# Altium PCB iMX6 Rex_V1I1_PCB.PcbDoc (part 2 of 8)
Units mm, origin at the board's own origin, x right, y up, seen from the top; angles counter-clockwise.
Board outline 70 x 40 mm, 12 copper layers (L1, L2, L3, L4, L5 (PWR), L6 (PWR), L7 (PWR), L8 (PWR), L9, L10, L11, L12), stack 1.566 mm thick; 473 components, 409 nets, 2294 pads, 1880 vias.
Unrouted connection lines stored in the file: 7.
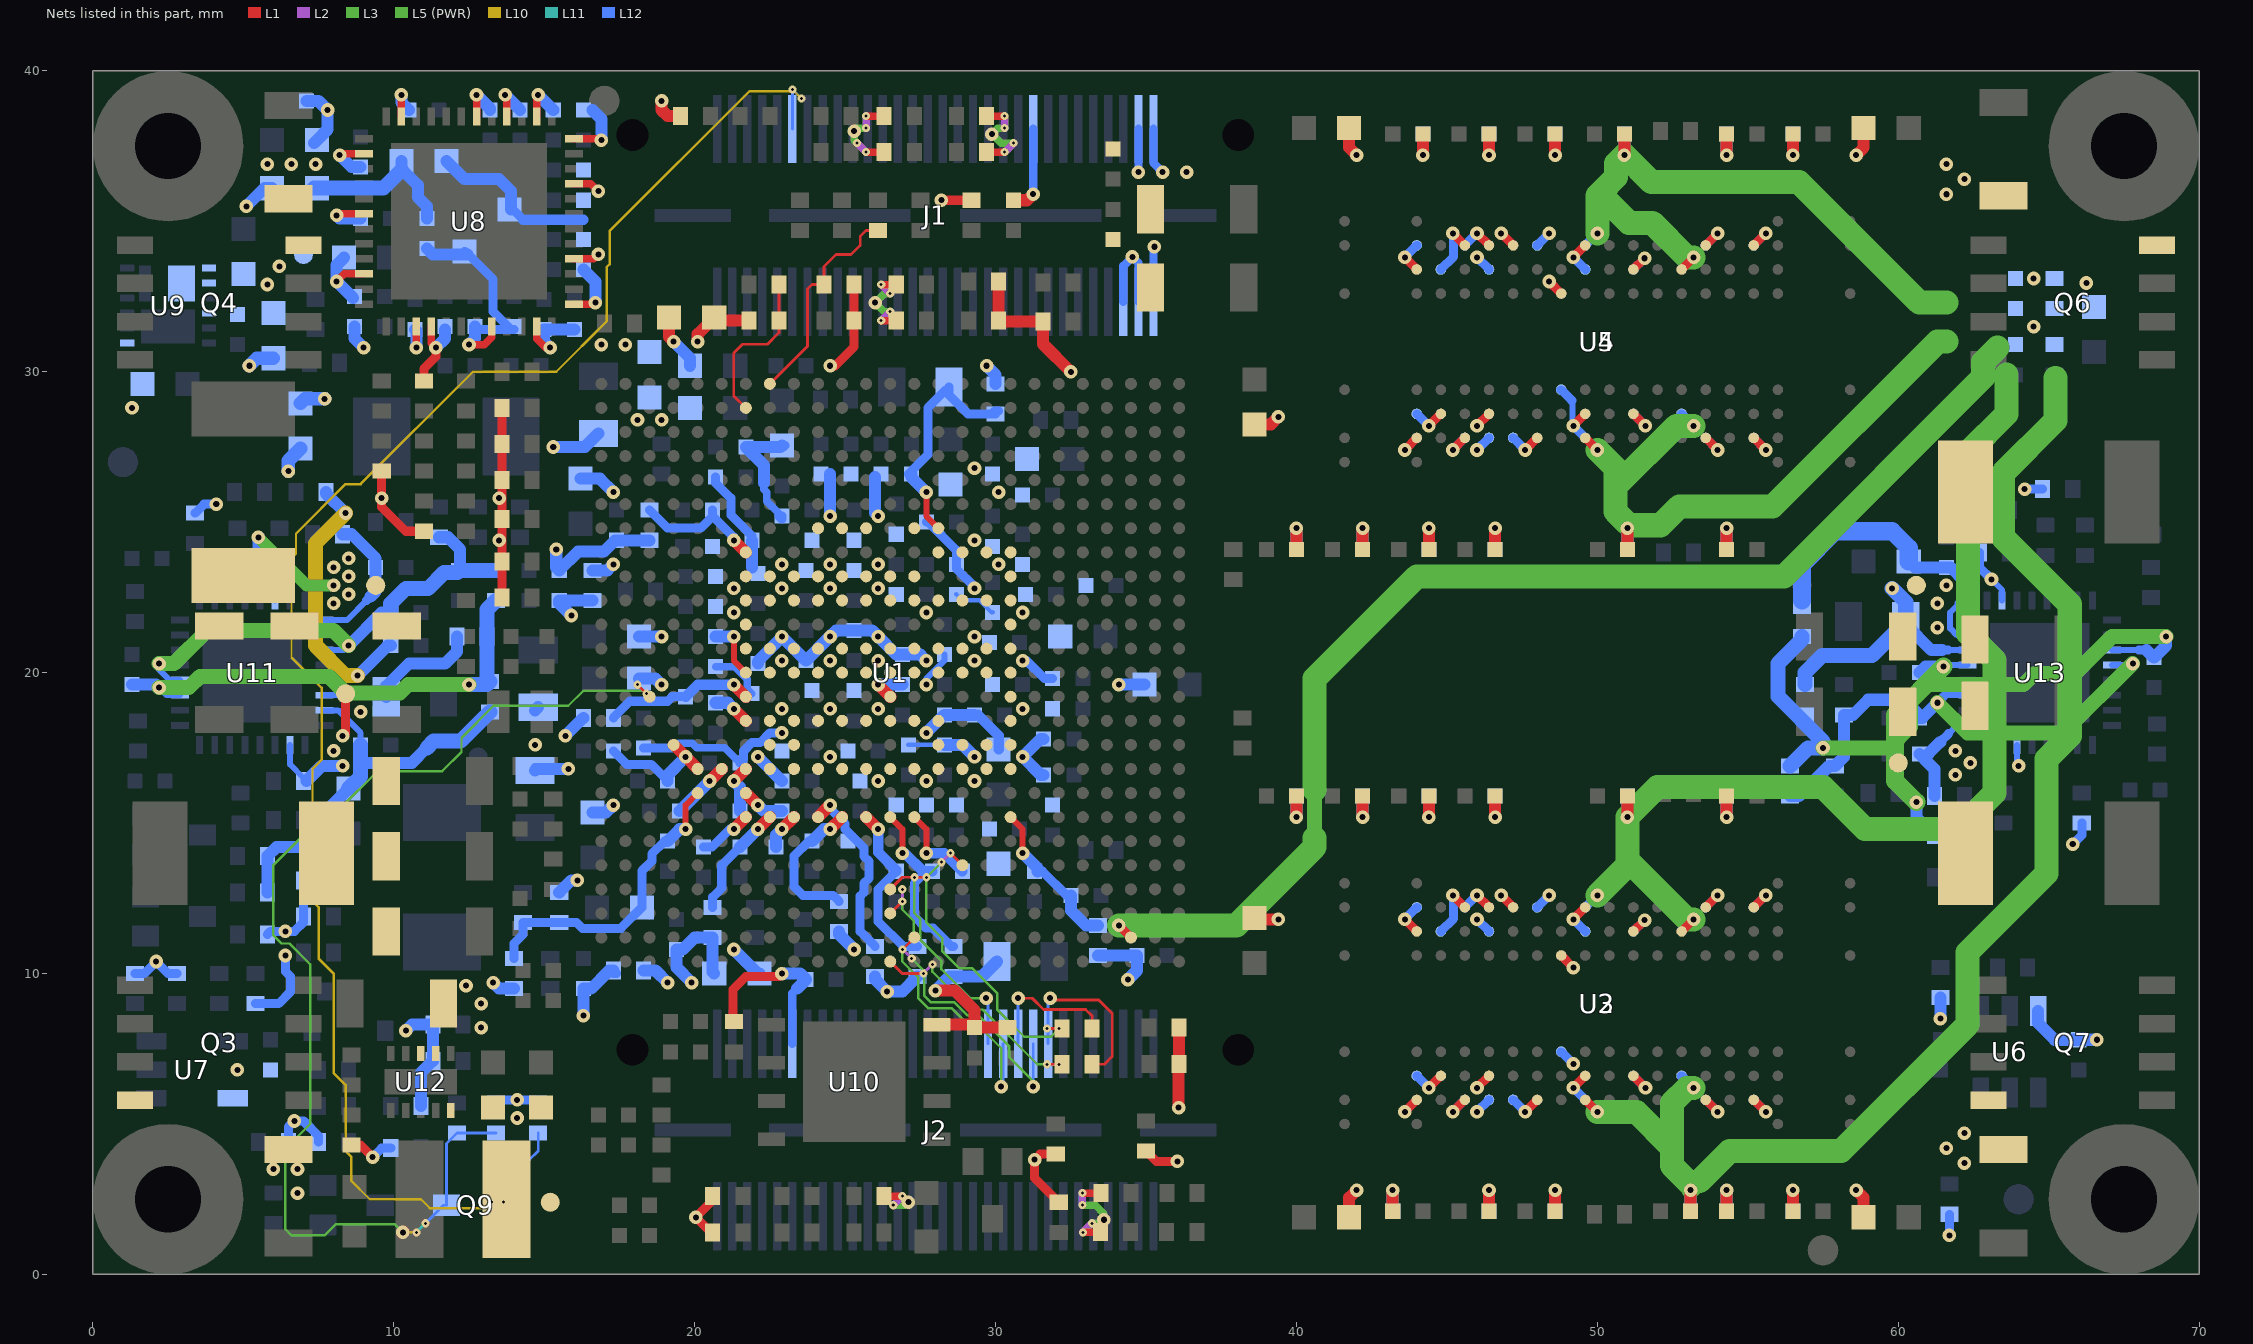
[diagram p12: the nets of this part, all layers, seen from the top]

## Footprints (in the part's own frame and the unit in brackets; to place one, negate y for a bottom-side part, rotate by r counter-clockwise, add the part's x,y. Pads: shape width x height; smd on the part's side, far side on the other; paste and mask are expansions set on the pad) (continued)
PBGA624 [mm] "Creator MM"
  round 0.4 smd mask+0.05: A2(-8.8,9.6) A3(-8,9.6) A4(-7.2,9.6) A5(-6.4,9.6) A6(-5.6,9.6) A7(-4.8,9.6) A8(-4,9.6) A9(-3.2,9.6) A10(-2.4,9.6) A11(-1.6,9.6) A12(-0.8,9.6) A13(0,9.6) A14(0.8,9.6) A15(1.6,9.6) A16(2.4,9.6) A17(3.2,9.6) A18(4,9.6) A19(4.8,9.6) A20(5.6,9.6) A21(6.4,9.6) A22(7.2,9.6) A23(8,9.6) A24(8.8,9.6) A25(9.6,9.6) AA1(-9.6,-6.4) AA2(-8.8,-6.4) AA3(-8,-6.4) AA4(-7.2,-6.4) AA5(-6.4,-6.4) AA6(-5.6,-6.4) AA7(-4.8,-6.4) AA8(-4,-6.4) AA9(-3.2,-6.4) AA10(-2.4,-6.4) AA11(-1.6,-6.4) AA12(-0.8,-6.4) AA13(0,-6.4) AA14(0.8,-6.4) AA15(1.6,-6.4) AA16(2.4,-6.4) AA17(3.2,-6.4) AA18(4,-6.4) AA19(4.8,-6.4) AA20(5.6,-6.4) AA21(6.4,-6.4) AA22(7.2,-6.4) AA23(8,-6.4) AA24(8.8,-6.4) AA25(9.6,-6.4) AB1(-9.6,-7.2) AB2(-8.8,-7.2) AB3(-8,-7.2) AB4(-7.2,-7.2) AB5(-6.4,-7.2) AB6(-5.6,-7.2) AB7(-4.8,-7.2) AB8(-4,-7.2) AB9(-3.2,-7.2) AB10(-2.4,-7.2) AB11(-1.6,-7.2) AB12(-0.8,-7.2) AB13(0,-7.2) AB14(0.8,-7.2) AB15(1.6,-7.2) AB16(2.4,-7.2) AB17(3.2,-7.2) AB18(4,-7.2) AB19(4.8,-7.2) AB20(5.6,-7.2) AB21(6.4,-7.2) AB22(7.2,-7.2) AB23(8,-7.2) AB24(8.8,-7.2) AB25(9.6,-7.2) AC1(-9.6,-8) AC2(-8.8,-8) AC3(-8,-8) AC4(-7.2,-8) AC5(-6.4,-8) AC6(-5.6,-8) AC7(-4.8,-8) AC8(-4,-8) AC9(-3.2,-8) AC10(-2.4,-8) AC11(-1.6,-8) AC12(-0.8,-8) AC13(0,-8) AC14(0.8,-8) AC15(1.6,-8) AC16(2.4,-8) AC17(3.2,-8) AC18(4,-8) AC19(4.8,-8) AC20(5.6,-8) AC21(6.4,-8) AC22(7.2,-8) AC23(8,-8) AC24(8.8,-8) AC25(9.6,-8) AD1(-9.6,-8.8) AD2(-8.8,-8.8) AD3(-8,-8.8) AD4(-7.2,-8.8) AD5(-6.4,-8.8) AD6(-5.6,-8.8) AD7(-4.8,-8.8) AD8(-4,-8.8) AD9(-3.2,-8.8) AD10(-2.4,-8.8) AD11(-1.6,-8.8) AD12(-0.8,-8.8) AD13(0,-8.8) AD14(0.8,-8.8) AD15(1.6,-8.8) AD16(2.4,-8.8) AD17(3.2,-8.8) AD18(4,-8.8) AD19(4.8,-8.8) AD20(5.6,-8.8) AD21(6.4,-8.8) AD22(7.2,-8.8) AD23(8,-8.8) AD24(8.8,-8.8) AD25(9.6,-8.8) AE1(-9.6,-9.6) AE2(-8.8,-9.6) AE3(-8,-9.6) AE4(-7.2,-9.6) AE5(-6.4,-9.6) AE6(-5.6,-9.6) AE7(-4.8,-9.6) AE8(-4,-9.6) AE9(-3.2,-9.6) AE10(-2.4,-9.6) AE11(-1.6,-9.6) AE12(-0.8,-9.6) AE13(0,-9.6) AE14(0.8,-9.6) AE15(1.6,-9.6) AE16(2.4,-9.6) AE17(3.2,-9.6) AE18(4,-9.6) AE19(4.8,-9.6) AE20(5.6,-9.6) AE21(6.4,-9.6) AE22(7.2,-9.6) AE23(8,-9.6) AE24(8.8,-9.6) AE25(9.6,-9.6) B1(-9.6,8.8) B2(-8.8,8.8) B3(-8,8.8) B4(-7.2,8.8) B5(-6.4,8.8) B6(-5.6,8.8) B7(-4.8,8.8) B8(-4,8.8) B9(-3.2,8.8) B10(-2.4,8.8) B11(-1.6,8.8) B12(-0.8,8.8) B13(0,8.8) B14(0.8,8.8) B15(1.6,8.8) B16(2.4,8.8) B17(3.2,8.8) B18(4,8.8) B19(4.8,8.8) B20(5.6,8.8) B21(6.4,8.8) B22(7.2,8.8) B23(8,8.8) B24(8.8,8.8) B25(9.6,8.8) C1(-9.6,8) C2(-8.8,8) C3(-8,8) C4(-7.2,8) C5(-6.4,8) C6(-5.6,8) C7(-4.8,8) C8(-4,8) C9(-3.2,8) C10(-2.4,8) C11(-1.6,8) C12(-0.8,8) C13(0,8) C14(0.8,8) C15(1.6,8) C16(2.4,8) C17(3.2,8) C18(4,8) C19(4.8,8) C20(5.6,8) C21(6.4,8) C22(7.2,8) C23(8,8) C24(8.8,8) C25(9.6,8) D1(-9.6,7.2) D2(-8.8,7.2) D3(-8,7.2) D4(-7.2,7.2) D5(-6.4,7.2) D6(-5.6,7.2) D7(-4.8,7.2) D8(-4,7.2) D9(-3.2,7.2) D10(-2.4,7.2) D11(-1.6,7.2) D12(-0.8,7.2) D13(0,7.2) D14(0.8,7.2) D15(1.6,7.2) D16(2.4,7.2) D17(3.2,7.2) D18(4,7.2) D19(4.8,7.2) D20(5.6,7.2) D21(6.4,7.2) D22(7.2,7.2) D23(8,7.2) D24(8.8,7.2) D25(9.6,7.2) E1(-9.6,6.4) E2(-8.8,6.4) E3(-8,6.4) E4(-7.2,6.4) E5(-6.4,6.4) E6(-5.6,6.4) E7(-4.8,6.4) E8(-4,6.4) E9(-3.2,6.4) E10(-2.4,6.4) E11(-1.6,6.4) E12(-0.8,6.4) E13(0,6.4) E14(0.8,6.4) E15(1.6,6.4) E16(2.4,6.4) E17(3.2,6.4) E18(4,6.4) E19(4.8,6.4) E20(5.6,6.4) E21(6.4,6.4) E22(7.2,6.4) E23(8,6.4) E24(8.8,6.4) E25(9.6,6.4) F1(-9.6,5.6) F2(-8.8,5.6) F3(-8,5.6) F4(-7.2,5.6) F5(-6.4,5.6) F6(-5.6,5.6) F7(-4.8,5.6) F8(-4,5.6) F9(-3.2,5.6) F10(-2.4,5.6) F11(-1.6,5.6) F12(-0.8,5.6) F13(0,5.6) F14(0.8,5.6) F15(1.6,5.6) F16(2.4,5.6) F17(3.2,5.6) F18(4,5.6) F19(4.8,5.6) F20(5.6,5.6) F21(6.4,5.6) F22(7.2,5.6) F23(8,5.6) F24(8.8,5.6) F25(9.6,5.6) G1(-9.6,4.8) G2(-8.8,4.8) G3(-8,4.8) G4(-7.2,4.8) G5(-6.4,4.8) G6(-5.6,4.8) G7(-4.8,4.8) G8(-4,4.8) G9(-3.2,4.8) G10(-2.4,4.8) G11(-1.6,4.8) G12(-0.8,4.8) G13(0,4.8) G14(0.8,4.8) G15(1.6,4.8) G16(2.4,4.8) G17(3.2,4.8) G18(4,4.8) G19(4.8,4.8) G20(5.6,4.8) G21(6.4,4.8) G22(7.2,4.8) G23(8,4.8) G24(8.8,4.8) G25(9.6,4.8) H1(-9.6,4) H2(-8.8,4) H3(-8,4) H4(-7.2,4) H5(-6.4,4) H6(-5.6,4) H7(-4.8,4) H8(-4,4) H9(-3.2,4) H10(-2.4,4) H11(-1.6,4) H12(-0.8,4) H13(0,4) H14(0.8,4) H15(1.6,4) H16(2.4,4) H17(3.2,4) H18(4,4) H19(4.8,4) H20(5.6,4) H21(6.4,4) H22(7.2,4) H23(8,4) H24(8.8,4) H25(9.6,4) J1(-9.6,3.2) J2(-8.8,3.2) J3(-8,3.2) J4(-7.2,3.2) J5(-6.4,3.2) J6(-5.6,3.2) J7(-4.8,3.2) J8(-4,3.2) J9(-3.2,3.2) J10(-2.4,3.2) J11(-1.6,3.2) J12(-0.8,3.2) J13(0,3.2) J14(0.8,3.2) J15(1.6,3.2) J16(2.4,3.2) J17(3.2,3.2) J18(4,3.2) J19(4.8,3.2) J20(5.6,3.2) J21(6.4,3.2) J22(7.2,3.2) J23(8,3.2) J24(8.8,3.2) J25(9.6,3.2) K1(-9.6,2.4) K2(-8.8,2.4) K3(-8,2.4) K4(-7.2,2.4) K5(-6.4,2.4) K6(-5.6,2.4) K7(-4.8,2.4) K8(-4,2.4) K9(-3.2,2.4) K10(-2.4,2.4) K11(-1.6,2.4) K12(-0.8,2.4) K13(0,2.4) K14(0.8,2.4) K15(1.6,2.4) K16(2.4,2.4) K17(3.2,2.4) K18(4,2.4) K19(4.8,2.4) K20(5.6,2.4) K21(6.4,2.4) K22(7.2,2.4) K23(8,2.4) K24(8.8,2.4) K25(9.6,2.4) L1(-9.6,1.6) L2(-8.8,1.6) L3(-8,1.6) L4(-7.2,1.6) L5(-6.4,1.6) L6(-5.6,1.6) L7(-4.8,1.6) L8(-4,1.6) L9(-3.2,1.6) L10(-2.4,1.6) L11(-1.6,1.6) L12(-0.8,1.6) L13(0,1.6) L14(0.8,1.6) L15(1.6,1.6) L16(2.4,1.6) L17(3.2,1.6) L18(4,1.6) L19(4.8,1.6) L20(5.6,1.6) L21(6.4,1.6) L22(7.2,1.6) L23(8,1.6) L24(8.8,1.6) L25(9.6,1.6) M1(-9.6,0.8) M2(-8.8,0.8) M3(-8,0.8) M4(-7.2,0.8) M5(-6.4,0.8) M6(-5.6,0.8) M7(-4.8,0.8) M8(-4,0.8) M9(-3.2,0.8) M10(-2.4,0.8) M11(-1.6,0.8) M12(-0.8,0.8) M13(0,0.8) M14(0.8,0.8) M15(1.6,0.8) M16(2.4,0.8) M17(3.2,0.8) M18(4,0.8) M19(4.8,0.8) M20(5.6,0.8) M21(6.4,0.8) M22(7.2,0.8) M23(8,0.8) M24(8.8,0.8) M25(9.6,0.8) N1(-9.6,0) N2(-8.8,0) N3(-8,0) N4(-7.2,0) N5(-6.4,0) N6(-5.6,0) N7(-4.8,0) N8(-4,0) N9(-3.2,0) N10(-2.4,0) N11(-1.6,0) N12(-0.8,0) N13(0,0) N14(0.8,0) N15(1.6,0) N16(2.4,0) N17(3.2,0) N18(4,0) N19(4.8,0) N20(5.6,0) N21(6.4,0) N22(7.2,0) N23(8,0) N24(8.8,0) N25(9.6,0) P1(-9.6,-0.8) P2(-8.8,-0.8) P3(-8,-0.8) P4(-7.2,-0.8) P5(-6.4,-0.8) P6(-5.6,-0.8) P7(-4.8,-0.8) P8(-4,-0.8) P9(-3.2,-0.8) P10(-2.4,-0.8) P11(-1.6,-0.8) P12(-0.8,-0.8) P13(0,-0.8) P14(0.8,-0.8) P15(1.6,-0.8) P16(2.4,-0.8) P17(3.2,-0.8) P18(4,-0.8) P19(4.8,-0.8) P20(5.6,-0.8) P21(6.4,-0.8) P22(7.2,-0.8) P23(8,-0.8) P24(8.8,-0.8) P25(9.6,-0.8) R1(-9.6,-1.6) R2(-8.8,-1.6) R3(-8,-1.6) R4(-7.2,-1.6) R5(-6.4,-1.6) R6(-5.6,-1.6) R7(-4.8,-1.6) R8(-4,-1.6) R9(-3.2,-1.6) R10(-2.4,-1.6) R11(-1.6,-1.6) R12(-0.8,-1.6) R13(0,-1.6) R14(0.8,-1.6) R15(1.6,-1.6) R16(2.4,-1.6) R17(3.2,-1.6) R18(4,-1.6) R19(4.8,-1.6) R20(5.6,-1.6) R21(6.4,-1.6) R22(7.2,-1.6) R23(8,-1.6) R24(8.8,-1.6) R25(9.6,-1.6) T1(-9.6,-2.4) T2(-8.8,-2.4) T3(-8,-2.4) T4(-7.2,-2.4) T5(-6.4,-2.4) T6(-5.6,-2.4) T7(-4.8,-2.4) T8(-4,-2.4) T9(-3.2,-2.4) T10(-2.4,-2.4) T11(-1.6,-2.4) T12(-0.8,-2.4) T13(0,-2.4) T14(0.8,-2.4) T15(1.6,-2.4) T16(2.4,-2.4) T17(3.2,-2.4) T18(4,-2.4) T19(4.8,-2.4) T20(5.6,-2.4) T21(6.4,-2.4) T22(7.2,-2.4) T23(8,-2.4) T24(8.8,-2.4) T25(9.6,-2.4) U1(-9.6,-3.2) U2(-8.8,-3.2) U3(-8,-3.2) U4(-7.2,-3.2) U5(-6.4,-3.2) U6(-5.6,-3.2) U7(-4.8,-3.2) U8(-4,-3.2) U9(-3.2,-3.2) U10(-2.4,-3.2) U11(-1.6,-3.2) U12(-0.8,-3.2) U13(0,-3.2) U14(0.8,-3.2) U15(1.6,-3.2) U16(2.4,-3.2) U17(3.2,-3.2) U18(4,-3.2) U19(4.8,-3.2) U20(5.6,-3.2) U21(6.4,-3.2) U22(7.2,-3.2) U23(8,-3.2) U24(8.8,-3.2) U25(9.6,-3.2) V1(-9.6,-4) V2(-8.8,-4) V3(-8,-4) V4(-7.2,-4) V5(-6.4,-4) V6(-5.6,-4) V7(-4.8,-4) V8(-4,-4) V9(-3.2,-4) V10(-2.4,-4) V11(-1.6,-4) V12(-0.8,-4) V13(0,-4) V14(0.8,-4) V15(1.6,-4) V16(2.4,-4) V17(3.2,-4) V18(4,-4) V19(4.8,-4) V20(5.6,-4) V21(6.4,-4) V22(7.2,-4) V23(8,-4) V24(8.8,-4) V25(9.6,-4) W1(-9.6,-4.8) W2(-8.8,-4.8) W3(-8,-4.8) W4(-7.2,-4.8) W5(-6.4,-4.8) W6(-5.6,-4.8) W7(-4.8,-4.8) W8(-4,-4.8) W9(-3.2,-4.8) W10(-2.4,-4.8) W11(-1.6,-4.8) W12(-0.8,-4.8) W13(0,-4.8) W14(0.8,-4.8) W15(1.6,-4.8) W16(2.4,-4.8) W17(3.2,-4.8) W18(4,-4.8) W19(4.8,-4.8) W20(5.6,-4.8) W21(6.4,-4.8) W22(7.2,-4.8) W23(8,-4.8) W24(8.8,-4.8) W25(9.6,-4.8) Y1(-9.6,-5.6) Y2(-8.8,-5.6) Y3(-8,-5.6) Y4(-7.2,-5.6) Y5(-6.4,-5.6) Y6(-5.6,-5.6) Y7(-4.8,-5.6) Y8(-4,-5.6) Y9(-3.2,-5.6) Y10(-2.4,-5.6) Y11(-1.6,-5.6) Y12(-0.8,-5.6) Y13(0,-5.6) Y14(0.8,-5.6) Y15(1.6,-5.6) Y16(2.4,-5.6) Y17(3.2,-5.6) Y18(4,-5.6) Y19(4.8,-5.6) Y20(5.6,-5.6) Y21(6.4,-5.6) Y22(7.2,-5.6) Y23(8,-5.6) Y24(8.8,-5.6) Y25(9.6,-5.6)
  silkscreen extent -10.6,-10.6 10.6,10.6, body extent -10.5,-10.5 10.5,10.5, height 1.1
QFN48_7MMX7MM [mm] "Creator MM"
  rect 0.6x0.25 smd mask+0.03: 1(-3.49,2.75) 2(-3.49,2.25) 3(-3.49,1.75) 4(-3.49,1.25) 5(-3.49,0.75) 6(-3.49,0.25) 7(-3.49,-0.25) 8(-3.49,-0.75) 9(-3.49,-1.25) 10(-3.49,-1.75) 11(-3.49,-2.25) 12(-3.49,-2.75) 25(3.49,-2.75) 26(3.49,-2.25) 27(3.49,-1.75) 28(3.49,-1.25) 29(3.49,-0.75) 30(3.49,-0.25) 31(3.49,0.25) 32(3.49,0.75) 33(3.49,1.25) 34(3.49,1.75) 35(3.49,2.25) 36(3.49,2.75)
  rect 0.25x0.6 smd mask+0.03: 13(-2.75,-3.49) 14(-2.25,-3.49) 15(-1.75,-3.49) 16(-1.25,-3.49) 17(-0.75,-3.49) 18(-0.25,-3.49) 19(0.25,-3.49) 20(0.75,-3.49) 21(1.25,-3.49) 22(1.75,-3.49) 23(2.25,-3.49) 24(2.75,-3.49) 37(2.75,3.49) 38(2.25,3.49) 39(1.75,3.49) 40(1.25,3.49) 41(0.75,3.49) 42(0.25,3.49) 43(-0.25,3.49) 44(-0.75,3.49) 45(-1.25,3.49) 46(-1.75,3.49) 47(-2.25,3.49) 48(-2.75,3.49)
  rect 5.2x5.2 smd paste-10 mask+0.025: 49(0,0)
  silkscreen extent -3.5,-3.5 3.5,3.5, body extent -3.51,-3.51 3.51,3.51, height 0.78
QSH-030-01-L-D-A [mm]
  rect 2.27x0.28 smd mask+0.051: 1(-2.87,7.25) 2(2.87,7.25) 3(-2.87,6.75) 4(2.87,6.75) 5(-2.87,6.25) 6(2.87,6.25) 7(-2.87,5.75) 8(2.87,5.75) 9(-2.87,5.25) 10(2.87,5.25) 11(-2.87,4.75) 12(2.87,4.75) 13(-2.87,4.25) 14(2.87,4.25) 15(-2.87,3.75) 16(2.87,3.75) 17(-2.87,3.25) 18(2.87,3.25) 19(-2.87,2.75) 20(2.87,2.75) 21(-2.87,2.25) 22(2.87,2.25) 23(-2.87,1.75) 24(2.87,1.75) 25(-2.87,1.25) 26(2.87,1.25) 27(-2.87,0.75) 28(2.87,0.75) 29(-2.87,0.25) 30(2.87,0.25) 31(-2.87,-0.25) 32(2.87,-0.25) 33(-2.87,-0.75) 34(2.87,-0.75) 35(-2.87,-1.25) 36(2.87,-1.25) 37(-2.87,-1.75) 38(2.87,-1.75) 39(-2.87,-2.25) 40(2.87,-2.25) 41(-2.87,-2.75) 42(2.87,-2.75) 43(-2.87,-3.25) 44(2.87,-3.25) 45(-2.87,-3.75) 46(2.87,-3.75) 47(-2.87,-4.25) 48(2.87,-4.25) 49(-2.87,-4.75) 50(2.87,-4.75) 51(-2.87,-5.25) 52(2.87,-5.25) 53(-2.87,-5.75) 54(2.87,-5.75) 55(-2.87,-6.25) 56(2.87,-6.25) 57(-2.87,-6.75) 58(2.87,-6.75) 59(-2.87,-7.25) 60(2.87,-7.25)
  rect 0.43x2.54 smd mask+0.076: 61(0,8.065) 64(0,-8.065)
  rect 0.43x4.7 smd mask+0.076: 62(0,3.175) 63(0,-3.175)
  round 0 hole 1.05 unplated: 65(2.67,10.065) 66(2.67,-10.065)
  silkscreen extent -3.68,-10.8 3.68,10.8, body extent -3.75,-10.64 3.75,10.64, height 3.42
R0402 [mm]
  rect 0.5x0.6 smd: 1(-0.5,0) 2(0.5,0)
  silkscreen extent -1,-0.6 1,0.6, body extent -0.5,-0.25 0.5,0.25, height 0.4
SC70_SOT323 [mm]
  rect 0.9x0.7 smd: 1(-0.95,0.65) 2(-0.95,-0.65) 3(0.95,0)
  silkscreen extent -0.7,-1.27 0.7,1.27, body extent -1.27,-1.27 1.27,1.27, height 1.1
SOD323 [mil]
  rect 22x27 smd mask+3: 1(-48,0) 2(48,0)
  silkscreen extent -75,-28 71,28, body extent -49,-25 49,25, height 39
TP_25C [mm]
  round 0.635 smd paste-0.635 mask+0.051: 1(0,0)
VLCF4020 [mm] "Creator MM"
  rect 1.6x3.9 smd paste-10: 1(-1.45,0)
  rect 1.6x3.9 smd paste-10 mask+0.1: 2(1.45,0)
  silkscreen extent -0.35,-2.1 0.35,2.1, body extent -2.15,-2 2.15,2, height 2.1
WSON8_6X5MM [mm] "Creator MM"
  rect 0.9x0.45 smd: 1(-2.75,1.905) 2(-2.75,0.635) 3(-2.75,-0.635) 4(-2.75,-1.905) 5(2.75,-1.905) 6(2.75,-0.635) 7(2.75,0.635) 8(2.75,1.905)
  rect 3.4x4 smd: 9(0,0)
  silkscreen extent -3.1,-2.6 3.1,2.8, body extent -3,-2.5 3,2.5, height 0.8

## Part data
C1 C206 C207 C225 C226: library part C1005X5R1C105K, "CAP CER 1.0UF 16V X5R 0402"
C2 C209 C210 C220 C228 C229 C241: library part GRM31CR6YA106KA12L, "CAP CER 10UF 35V X5R 1206"
C3 C4 C5 C6 C8 C9 C10 C11 C21 C22 C23 C24 C25 C26 C27 C28 C29 C30 C31 C32 C33 C34 C35 C36 C37 C38 C39 C40 C41 C42 C43 C44 C45 C46 C47 C48 C49 C50 C51 C52 C53 C54 C55 C56 C57 C58 C59 C60 C61 C62 C64 C68 C73 C75 C76 C77 C79 C81 C82 C90 C91 C92 C93 C94 C95 C97 C98 C99 C100 C102 C103 C104 C105 C107 C108 C109 C110 C112 C113 C114 C115 C116 C117 C119 C120 C121 C122 C123 C124 C125 C126 C130 C131 C132 C133 C134 C136 C138 C140 C142 C143 C144 C145 C146 C149 C150 C152 C153 C154 C155 C157 C158 C159 C160 C161 C162 C163 C164 C165 C166 C167 C168 C169 C170 C171 C174: library part C1005X5R1E224M, "CAP CER .22UF 25V X5R 20% 0402"
C7 C18 C20 C63 C65 C66 C67 C74 C87 C88 C89 C181 C187 C190 C192 C195 C203 C205 C211 C212 C219 C224 C230 C231 C238 C239 C240 C242: library part C1005X5R1H104K, "CAP CER .10UF 50V X5R 10% 0402"
C12 C13 C14 C15 C16 C17 C96 C101 C106 C111 C118 C127 C128 C129 C135 C151 C172 C173: library part GRM188R60G226MEA0L, "CAP CER 22UF 4V 20% X5R 0603"
C19 C80 C177 C178 C180 C186 C191 C194 C199 C204 C221 C222 C223: library part C1608X5R0J106M, "CAP CER 10UF 6.3V X5R 20% 0603"
C69 C70 C71 C72 C139: library part C1005X7R1H103K, "CAP CER 10000PF 50V 10% X7R 0402"
C78 C243 C244 C245 C246 C247: library part C1005X5R1A475M, "CAP CER 4.7UF 10V 20% X5R 0402"
C83 C84 C85 C86: library part C1005C0G1H180J, "CAP CER 18PF 50V C0G 5% 0402"
C137 C141 C147 C148 C156: library part C2012X5R1C226K, "CAP CER 22UF 16V 10% X5R 0805"
C175 C176: library part C1005C0G1H220J, "CAP CER 22PF 50V C0G 5% 0402"
C179: library part GRM1555C1H561JA01D, "CAP CER 560PF 50V C0G 0402"
C182 C183 C184 C185 C188 C189 C193 C196 C197 C198 C200 C201 C202 C218 C237 C248 C249: library part C1005X7R1C103K, "CAP CER 10000PF 16V X7R 10% 0402"
C208 C227: library part GRM21BR71H105KA12L, "CAP CER 1UF 50V X7R 0805"
C213 C214 C215 C216 C217 C232 C233 C234 C235 C236: library part C3216X5R1A107M, "CAP CER 100UF 10V X5R 20% 1206"
D1: "DIODE SCHTKY 30MA 30V SOD-323"
D2: library part "LG L29K-G2J1-24-Z", "LED SMARTLED GREEN 570NM 0603"
D3: library part "LO L29K-H2K1-24-Z", "LED SMARTLED ORANGE 606NM 0603"
FB1 FB2 FB8: library part BLM18SG221TN1D, "FERRITE CHIP 220 OHM 2500MA 0603"
FB3 FB4 FB6 FB7: "FERRITE CHIP 100 OHM BEAD 0603 3A"
FB5: "FERRITE CHIP 600 OHM 0402 420mA"
FID1 FID2 FID3 FID4: "Fiducial 40mil Diameter, 52mil Mask"
J1 J2: "CONN RCPT HI-SPD .5MM 60POS DL"
L1: library part IHLP2525CZER4R7M01, "INDUCTOR POWER 4.7UH 5.5A SMD"
L2 L4 L5: library part IHLP2525CZER3R3M01, "INDUCTOR POWER 3.3UH 6A SMD"
L3: "INDUCTOR POWER 10UH .85A SMD"
MH1 MH2 MH3 MH4: "Mounting Hole 5mm Diameter, 2.2mm Drill"
Q1 Q2 Q5 Q8 Q9: "MOSFET N-CH 60V 310MA SOT323"
Q3 Q4 Q6 Q7: "MOSFET DL N-CH 30V 6.8A 8-SOIC"
R1 R35 R36 R50 R52 R66 R72 R83 R85 R86 R90 R92 R112 R159 R160 R161: library part RC0402FR-0722RL, "RES 22.0 OHM 1/16W 1% 0402 SMD"
R2 R3 R15: library part CRCW0402200RFKED, "RES 200 OHM 1/16W 1% 0402 SMD"
R4 R5 R8 R9 R10 R11 R12: library part RMCF0402FT240R, "RES TF 240 OHM 1% 0.0625W 0402"
R6 R7 R33 R38 R39 R40 R41 R42 R43 R48 R49 R57 R58 R60 R62 R63 R64 R67 R68 R69 R75 R91 R94 R95 R96 R97 R98 R100 R103 R104 R109 R110 R115 R127 R129 R130 R131 R132 R133 R136 R151 R153 R154 R155 R158 R165: library part RC0402FR-0710KL, "RES 10.0K OHM 1/16W 1% 0402 SMD"
R13 R14 R18 R19 R23 R24 R25 R26 R27 R34 R51 R65 R70 R71 R74 R76 R78 R80 R88 R93 R105 R106 R107 R108 R116 R117 R128 R140 R141 R152 R156 R157 R163 R164: library part RC0402JR-070RL, "RES 0.0 OHM 1/16W 0402 SMD"
R16 R17: library part RC0402FR-0749R9L, "RES 49.9 OHM 1/16W 1% 0402 SMD"
R20: library part CRCW0402191RFKED, "RES 191 OHM 1/16W 1% 0402 SMD"
R21 R22: library part RC0402FR-0747KL, "RES 47.0K OHM 1/16W 1% 0402 SMD"
R28 R29 R31 R32 R44 R45 R46 R47 R55 R56 R59 R84 R87 R89 R120: library part RMCF0402FT4K99, "RES TF 4.99K OHM 1% 1/16W 0402"
R30: library part ERJ-2RKF1601X, "RES 1.6K OHM 1/10W 1% 0402 SMD"
R37: library part CRCW04022M20FKED, "RES 2.20M OHM 1/16W 1% 0402 SMD"
R53 R54: library part CRCW040210M0FKED, "RES 10.0M OHM 1/16W 1% 0402 SMD"
R61 R99 R101 R102 R162: library part RC0402FR-071KL, "RES 1.00K OHM 1/16W 1% 0402 SMD"
R73 R111 R137 R143 R144: library part RMCF0402FT100K, "RES 100K OHM 1/16W 1% 0402 SMD"
R77: library part CRCW04022R20FKED, "RES 2.20 OHM 1/16W 1% 0402 SMD"
R79 R118 R142: library part RC0402FR-0710RL, "RES 10.0 OHM 1/16W 1% 0402 SMD"
R81 R82 R113 R114: library part RC0402FR-07220RL, "RES 220 OHM 1/16W 1% 0402 SMD"
R119: library part RC0402FR-0714KL, "RES 14.0K OHM 1/16W 1% 0402 SMD"
R121 R122 R145 R146: library part RC0402FR-071RL, "RES 1.00 OHM 1/16W 1% 0402 SM"
R123: library part RC0402FR-0739KL, "RES 39.0K OHM 1/16W 1% 0402 SMD"
R124 R125 R148 R149: library part RC0402FR-07200KL, "RES 200K OHM 1/16W 1% 0402 SMD"
R126 R150: library part CRCW040210K5FKED, "RES 10.5K OHM 1/16W 1% 0402 SMD"
R134: library part RC0402FR-0712KL, "RES 12.0K OHM 1/16W 1% 0402 SMD"
R135: library part RC0402FR-073K3L, "RES 3.30K OHM 1/16W 1% 0402 SMD"
R138: library part CRCW0402330KFKED, "RES 330K OHM 1/16W 1% 0402 SMD"
R139: library part RC0402FR-07120KL, "RES 120K OHM 1/16W 1% 0402 SMD"
R147: library part RC0402FR-0727KL, "RES 27.0K OHM 1/16W 1% 0402 SMD"
TP3 TP5 TP6 TP7 TP8 TP9 TP10 TP11: "Test Point 25mil"
U1: "IC MCU 32BIT ARM QUAD 624FCBGA"
U2 U3 U4 U5: "IC DDR3 SDRAM 2GBIT 667MHZ 96BGA"
U6: library part TPS3808G09DBVR, "IC VOLT SUPERVISOR 0.9V SOT23-6"
U7: "IC GATE AND SGL 2INP SOT23-5"
U8: "IC TXRX 10/100/1000 SGL 48QFN"
U9: "IC PWM REG 600mA 1.2V 12-MLF"
U10: library part SST25VF016B-75-4I-QAF, "IC FLASH 16MBIT 75MHZ 8WSON"
U11 U13: "IC MAIN PWR CTRLR QUAD 32-QFN"
U12: "IC REG BUCK SYNC ADJ 0.5A 10WSON"
Y1: library part ABM7-24.000MHZ-D-2-Y-T, "CRYSTAL 24.0000MHZ 18PF SMD"
Y2: library part ABS06-32.768KHZ-9-1-T, "CRYSTAL 32.768 KHZ 9.0 PF SMD"
Y3: library part "ABM7-25.000MHZ-D-2-Y-T V1.1", "CRYSTAL 25.0000 MHZ 18PF SMD"

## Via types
v1: diameter 0.45, hole 0.2, L1 to L12, tented both sides, 761 vias
v2: diameter 0.27, hole 0.1, L1 to L2, 305 vias
v3: diameter 0.27, hole 0.1, L2 to L3, 290 vias
v4: diameter 0.45, hole 0.2, L3 to L10, 196 vias
v5: diameter 0.27, hole 0.1, L11 to L12, 185 vias
v6: diameter 0.27, hole 0.1, L10 to L11, 142 vias
v7: diameter 0.45, hole 0.2, L3 to L10, tented both sides, 1 vias

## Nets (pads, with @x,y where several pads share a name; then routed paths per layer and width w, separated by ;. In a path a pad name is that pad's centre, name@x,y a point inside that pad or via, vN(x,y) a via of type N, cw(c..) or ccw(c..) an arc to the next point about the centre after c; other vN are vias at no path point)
+1V1_NVCC_PLL_OUT: C150.1 C151.1 R77.2 R79.2 R105.1 U1.E8 | length 10.4
  L1 w0.2: v1(19.7,14.8) 19.7,15.6 U1.E8@20.1,16
  L12 w0.3: R77.2@14,10.5 14,11 14.3,11.3 R79.2@14.3,11.7 R105.1@15.5,11.7 16.072,11.7 16.272,11.5 17.55,11.5 C151.1@18.25,12.2 18.25,13.412 18.575,13.737 18.575,13.975 C150.1@19,14.4 ; C150.1@19.05,14.35 C150.1@19.1,14.4
  L12 w0.4: C150.1@19.1,14.4 19.5,14.8 v1(19.7,14.8)
+1V1_VDDSOC_CAP: C78.1 C112.1 C113.1 C114.1 C115.1 C116.1 C117.1 C118.1 C138.1 C246.1 FB1.1 R13.1 R18.1 R23.1 U1.N12 U1.R10 U1.T10 U1.T13 U1.T14 U1.U10 U1.U13 U1.U14 | length 11.6
  L1 w0.4: v1(26.1,19.6) U1.N12@26.5,19.2
  L12 w0.15: C116.1@27.1,17.6 C115.1@28.3,17.6 ; C113.1@28.7,22.6 28.9,22.4 29.466,22.4 29.866,22 C114.1@29.9,22
  L12 w0.4: v1(15.9,21.9) 15.5,22.3 C246.1@15.5,22.4 R18.1@16.6,22.4 ; v1(19.9,9.7) 19.4,10.2 C78.1@19.4,10.8 19.6,10.8 20,11.2 R13.1@20.6,11.2 20.6,10.05 FB1.1@20.65,10 ; R23.1@24.8,11.4 24.8,11.3 v1(25.3,10.8) ; v1(26.1,19.6) C138.1@26.9,19.6 ; C115.1@28.3,17.6 28.9,17.6 v1(29.3,17.2)
  other v1: 29.3,20.4 29.3,21.2
+1V2_ETH: C178.1 C179.1 FB3.1 FB4.1 FB5.1 FB8.1 R105.2 TP5.1 U9.7 U9.8 U9.10 U9.15 | length 6.2
  L12 w0.4: FB4.1@10.25,37 10.25,36.75 10.8,36.2 10.8,35.8 11.1,35.5 FB5.1@11.1,35.1 ; R105.2@15.5,12.7 15.9,13.1 v1(16.1,13.1)
  L12 w0.5: FB3.1@7.35,36.1 9.65,36.1 FB4.1@10.25,36.7
  other v1: 5.8,32.9 6.2,33.5
+1V2_ETH_AVDDL: C186.1 C187.1 C188.1 C189.1 FB4.2 U8.4 U8.9 | length 7.5
  L1 w0.25: U8.4@15.99,33.75 16.65,33.75 v1(16.8,33.9) ; U8.9@15.99,36.25 16.55,36.25 v1(16.8,36)
  L12 w0.3: C186.1@13.85,35.4 13.9,35.4 13.95,35.4 14.3,35.05
  L12 w0.35: 14.3,35.05 16.3,35.05
  L12 w0.4: FB4.2@11.75,37 12.35,36.4 13.5,36.4 13.9,36 C186.1@13.9,35.4
+1V2_ETH_AVDDL_PLL: C191.1 C192.1 C193.1 FB5.2 U8.44 | length 7.5
  L1 w0.25: v1(12.5,30.9) 13,30.9 13.25,31.15
  L12 w0.3: C191.1@12.35,34 12.372,34 13.3,33.072 13.3,32 C192.1@13.9,31.4 ; C193.1@12.7,31.4 C192.1@13.9,31.4 ; C192.1@14,31.4 C192.1@13.9,31.4
  L12 w0.4: FB5.2@11.1,34.1 11.3,33.9 C191.1@12.45,33.9 ; v1(12.5,30.9) 12.7,31.1 12.7,31.4 C193.1@12.7,31.5
+1V2_ETH_DVDDL: C180.1 C181.1 C182.1 C183.1 C184.1 C185.1 C248.1 C249.1 FB3.2 U8.14 U8.18 U8.23 U8.26 U8.30 U8.39 | length 11.8
  L1 w0.25: v1@8.1,35.1 8.25,35.25 U8.30@9.01,35.25 ; v1@8.2,37.25 8.7,37.25 ; U8.23@10.25,38.49 v1(10.25,39.2) ; v1(10.75,30.8) U8.39@10.75,31.51 ; U8.18@12.75,38.49 v1(12.75,39.2) ; U8.14@14.75,38.49 v1@14.75,39.15
  L12 w0.4: v1(5.1,35.5) 5.7,36.1 FB3.2@5.95,36.1 ; C181.1@7.1,39 7.5,39 v1(7.8,38.7) 7.8,38.05 C180.1@7.45,37.7 C180.1@7.35,37.6 ; v1(8.1,35.2) 8.2,35.1 C183.1@8.9,35.1 ; v1(8.2,37.2) 8.6,36.8 C184.1@8.9,36.8 ; v1(10.25,39.2) 10.25,38.95 C249.1@10.5,38.7 ; C182.1@10.7,31.4 10.75,31.35 v1(10.75,30.8) ; v1(12.75,39.2) 13.2,38.75 C248.1@13.2,38.7 ; v1(14.8,39.2) C185.1@15.3,38.7
+1V2_VDD_ARM_CAP: C97.1 C98.1 C99.1 C100.1 C101.1 C102.1 C103.1 C104.1 C105.1 C106.1 U1.H11 U1.H13 U1.J11 U1.J13 U1.K11 U1.K13 U1.L11 U1.L13 U1.M11 U1.M13 U1.N11 U1.N13 U1.P11 U1.P13 U1.R11 U1.R13 | length 7.2
  L12 w0.2: v1(27.7,19.6) 27.7,19.799 28.3,20.399 C97.1@28.3,20.6
  L12 w0.25: C98.1@20.7,20.2 21.336,20.2 21.75,19.786 21.75,19.45 C103.1@21.9,19.3
  L12 w0.35: C102.1@29.3,18.6 29.407,18.6 30.1,17.907 C106.1@30.1,17.45
  L12 w0.4: C101.1@18.15,19.8 18.7,19.8 v1(18.9,19.6) ; v1(27.7,18) C105.1@28.3,18.6 C102.1@29.3,18.6
  other v1: 22.9,18.8 24.5,18.8 26.1,18.8 22.9,20.4 24.5,20.4 26.1,20.4
+1V5_DDR: C12.1 C13.1 C14.1 C15.1 C16.1 C17.1 C18.1 C19.1 C21.1 C22.1 C23.1 C24.1 C25.1 C26.1 C27.1 C28.1 C29.1 C30.1 C31.1 C32.1 C33.1 C34.1 C35.1 C36.1 C37.1 C38.1 C39.1 C40.1 C41.1 C42.1 C43.1 C44.1 C45.1 C46.1 C47.1 C48.1 C49.1 C50.1 C51.1 C52.1 C53.1 C54.1 C55.1 C56.1 C57.1 C58.1 C59.1 C60.1 C157.1 C158.1 C159.1 C160.1 C161.1 C162.1 C167.1 C168.1 C169.1 C170.1 C171.1 C172.1 C173.1 C235.1 C236.1 L5.2 R11.2 R59.2 TP9.1 U1.R18 U1.T18 U1.U18 U1.V9 U1.V10 U1.V11 U1.V12 U1.V13 U1.V14 U1.V15 U1.V16 U1.V17 U1.V18 U2.A1 U2.A8 U2.B2 U2.C1 U2.C9 U2.D2 U2.D9 U2.E9 U2.F1 U2.G7 U2.H2 U2.H9 U2.K2 U2.K8 U2.N1 U2.N9 U2.R1 U2.R9 U3.A1 U3.A8 U3.B2 U3.C1 U3.C9 U3.D2 U3.D9 U3.E9 U3.F1 U3.G7 U3.H2 U3.H9 U3.K2 U3.K8 U3.N1 U3.N9 U3.R1 U3.R9 U4.A1 U4.A8 U4.B2 U4.C1 U4.C9 U4.D2 U4.D9 U4.E9 U4.F1 U4.G7 U4.H2 U4.H9 U4.K2 U4.K8 U4.N1 U4.N9 U4.R1 U4.R9 U5.A1 U5.A8 U5.B2 U5.C1 U5.C9 U5.D2 U5.D9 U5.E9 U5.F1 U5.G7 U5.H2 U5.H9 U5.K2 U5.K8 U5.N1 U5.N9 U5.R1 U5.R9 U13.30 | length 83
  L1 w0.3: v1(43.6,5.4) U2.A1@44,5.8 ; v1(43.6,11.8) U2.A8@44,11.4 ; v1(43.6,33.8) U4.A8@44,33.4 ; v1@43.625,27.425 U4.A1@44,27.8 ; v1(44.4,6.2) U2.B2@44.8,6.6 ; v1(44.4,28.2) U4.B2@44.8,28.6 ; v1(45.2,5.4) U2.C1@45.6,5.8 ; v1(45.2,12.6) U2.C9@45.6,12.2 ; v1(45.2,27.4) U4.C1@45.6,27.8 ; v1(45.2,34.6) U4.C9@45.6,34.2 ; v1(46,6.2) U2.D2@46.4,6.6 ; v1(46,12.6) U2.D9@46.4,12.2 ; v1(46,28.2) U4.D2@46.4,28.6 ; v1(46,34.6) U4.D9@46.4,34.2 ; v1(46.8,12.6) U2.E9@47.2,12.2 ; v1(46.8,34.6) U4.E9@47.2,34.2 ; v1(47.6,5.4) U2.F1@48,5.8 ; v1(47.6,27.4) U4.F1@48,27.8 ; v1(48.4,33) U4.G7@48.8,32.6 ; U2.G7@48.8,10.6 v1(49.2,10.2) ; v1(49.2,6.2) U2.H2@49.6,6.6 ; v1(49.2,11.8) U2.H9@49.6,12.2 ; v1(49.2,28.2) U4.H2@49.6,28.6 ; v1(49.2,33.8) U4.H9@49.6,34.2 ; U2.K2@51.2,6.6 v1(51.6,6.2) ; U2.K8@51.2,11.4 v1(51.573,11.773) ; U4.K2@51.2,28.6 v1(51.6,28.2) ; U4.K8@51.2,33.4 v1(51.573,33.773) ; U2.N1@53.6,5.8 v1(54,5.4) ; U2.N9@53.6,12.2 v1(54,12.6) ; U4.N1@53.6,27.8 v1(54,27.4) ; U4.N9@53.6,34.2 v1(54,34.6) ; U2.R1@55.2,5.8 v1(55.6,5.4) ; U2.R9@55.2,12.2 v1(55.6,12.6) ; U4.R1@55.2,27.8 v1(55.6,27.4) ; U4.R9@55.2,34.2 v1(55.6,34.6)
  L1 w0.4: C12.1@38.6,11.85 38.65,11.8 v1(39.4,11.8) ; C17.1@38.6,28.25 39.15,28.25 v1(39.4,28.5) ; v1(40,15.2) C26.1@40,15.9 ; C39.1@40,24.1 v1(40,24.8) ; C14.1@41.75,1.9 41.75,2.55 v1(42,2.8) ; C15.1@41.75,38.1 41.75,37.45 v1(42,37.2) ; v1(42.2,15.2) C24.1@42.2,15.9 ; C40.1@42.2,24.1 v1(42.2,24.8) ; C27.1@43.2,2.1 v1(43.2,2.8) ; v1(44.2,37.2) C36.1@44.2,37.9 ; v1(44.4,15.2) C25.1@44.4,15.9 ; C31.1@44.4,24.1 v1(44.4,24.8) ; C28.1@46.4,2.1 v1(46.4,2.8) ; v1(46.4,37.2) C37.1@46.4,37.9 ; v1(46.6,15.2) C23.1@46.6,15.9 ; C33.1@46.6,24.1 v1(46.6,24.8) ; C29.1@48.6,2.1 v1(48.6,2.8) ; v1(48.6,37.2) C34.1@48.6,37.9 ; C30.1@54.3,2.1 v1(54.3,2.8) ; v1(54.3,15.2) C22.1@54.3,15.9 ; C32.1@54.3,24.1 v1(54.3,24.8) ; v1(54.3,37.2) C38.1@54.3,37.9 ; C21.1@56.5,2.1 v1(56.5,2.8) ; v1(56.5,37.2) C35.1@56.5,37.9 ; v1(58.6,2.8) 58.85,2.55 C13.1@58.85,1.9 ; v1(58.6,37.2) 58.85,37.45 C16.1@58.85,38.1
  L12 w0.2: 49.15,29.05 49.175,29.025 49.175,28.225 v1(49.2,28.2) ; U13.30@63.95,17.6 63.95,16.95 v1(64,16.9)
  L12 w0.3: v1(30.9,20.4) 31.028,20.4 31.628,19.8 C170.1@31.9,19.8 ; v1(34.1,19.6) C172.1@34.95,19.6 ; v1(43.6,11.8) U3.A1@44,12.2 ; v1(43.6,33.8) U5.A1@44,34.2 ; U3.A8@44,6.6 v1(44.4,6.2) ; U5.A8@44,28.6 v1(44.4,28.2) ; U3.B2@44.8,11.4 45.225,11.825 v1@45.225,12.575 ; U5.B2@44.8,33.4 45.225,33.825 45.225,34.575 v1(45.2,34.6) ; v1(45.2,5.4) U3.C9@45.6,5.8 ; v1(45.2,27.4) U5.C9@45.6,27.8 ; U3.C1@45.6,12.2 v1(46,12.6) ; U5.C1@45.6,34.2 v1(46,34.6) ; v1(46,5.4) U3.D9@46.4,5.8 ; v1(46,11.8) U3.D2@46.4,11.4 ; v1(46,27.4) U5.D9@46.4,27.8 ; v1(46,33.8) U5.D2@46.4,33.4 ; U3.E9@47.2,5.8 v1(47.6,5.4) ; U5.E9@47.2,27.8 v1(47.6,27.4) ; U3.F1@48,12.2 v1(48.4,12.6) ; U5.F1@48,34.2 v1(48.4,34.6) ; U5.G7@48.8,29.4 49.15,29.05 ; U3.G7@48.8,7.4 v1(49.2,7) ; v1(49.2,6.2) U3.H9@49.6,5.8 ; v1(49.2,11.8) U3.H2@49.6,11.4 ; v1(49.2,28.2) U5.H9@49.6,27.8 ; v1(49.2,33.8) U5.H2@49.6,33.4 ; U3.K8@51.2,6.6 v1(51.6,6.2) ; U3.K2@51.2,11.4 v1(51.573,11.773) ; U5.K8@51.2,28.6 v1(51.6,28.2) ; U5.K2@51.2,33.4 v1(51.573,33.773) ; U3.N9@53.6,5.8 v1(54,5.4) ; U3.N1@53.6,12.2 v1(54,12.6) ; U5.N9@53.6,27.8 v1(54,27.4) ; U5.N1@53.6,34.2 v1(54,34.6) ; U3.R9@55.2,5.8 v1(55.6,5.4) ; U3.R1@55.2,12.2 v1(55.6,12.6) ; U5.R9@55.2,27.8 v1(55.6,27.4) ; U5.R1@55.2,34.2 v1(55.6,34.6)
  L12 w0.4: C158.1@31.6,16.6 31.5,16.6 v1(30.9,17.2) 31.5,17.8 C162.1@31.6,17.8 ; v1(34.1,19.6) C172.1@34.95,19.6 ; v1(40,15.2) C46.1@40,15.9 ; C60.1@40,24.1 v1(40,24.8) ; v1(42.2,15.2) C43.1@42.2,15.9 ; C51.1@42.2,24.1 v1(42.2,24.8) ; C47.1@43.2,2.1 v1(43.2,2.8) ; v1(44.2,37.2) C57.1@44.2,37.9 ; v1(44.4,15.2) C45.1@44.4,15.9 ; C53.1@44.4,24.1 v1(44.4,24.8) ; C49.1@46.4,2.1 v1(46.4,2.8) ; v1(46.4,37.2) C56.1@46.4,37.9 ; v1(46.6,15.2) C44.1@46.6,15.9 ; C52.1@46.6,24.1 v1(46.6,24.8) ; C48.1@48.6,2.1 v1(48.6,2.8) ; v1(48.6,37.2) C59.1@48.6,37.9 ; C50.1@54.3,2.1 v1(54.3,2.8) ; v1(54.3,15.2) C42.1@54.3,15.9 ; C54.1@54.3,24.1 v1(54.3,24.8) ; v1(54.3,37.2) C58.1@54.3,37.9 ; C41.1@56.5,2.1 v1(56.5,2.8) ; v1(56.5,37.2) C55.1@56.5,37.9 ; v1(61.4,8.5) R59.2@61.4,9.2
  other v1: 61.9,16.6 62.4,17 61.9,17.4 30.9,18.8 30.9,22 30.1,23.6 29.3,24.4 30.1,26 43.6,27.4 66.25,32.95 64.5,33.1
+1V375: C90.1 C91.1 C92.1 C93.1 C94.1 C95.1 C96.1 C107.1 C108.1 C109.1 C110.1 C111.1 C216.1 C217.1 C232.1 FB2.2 FB8.2 L2.2 R77.1 TP7.1 U1.H14 U1.J14 U1.K9 U1.K14 U1.L9 U1.L14 U1.M9 U1.M14 U1.N9 U1.N14 U1.P9 U1.P14 U1.R9 U1.R14 U1.T9 U1.U9 U11.30 | length 15.1
  L3 w0.4: v1(5.5,24.5) 7.1,22.9 v1(8,22.9)
  L12 w0.2: 5.9,23.1 6.05,22.95 U11.30@6.05,22.4
  L12 w0.3: 5.5,23.6 5.5,23.5 5.9,23.1
  L12 w0.4: 5.5,23.6 v1(5.5,24.5) ; v1(13.3,9.7) 13.5,9.5 R77.1@14,9.5 ; C111.1@18.15,21.2 v1(18.9,21.2) ; C92.1@22.1,20.3 22.1,20.376 22.9,21.176 v1(22.9,21.2) C93.1@23.7,20.4 v1(24.5,21.2) 24.7,21.4 C94.1@25.3,21.4 25.9,21.4 v1(26.1,21.2) 26.7,20.6 C95.1@26.9,20.6 27.5,20.6 v1(27.7,20.4)
  L12 w0.45: v1(5.2,30.2) 5.45,30.45 FB8.2@6,30.45
  other v1: 26.1,16.4 27.7,16.4 29.3,16.4 24.5,17.2 8,22.3 8.5,22.6 8.5,23.2 8,23.5 8.5,23.8 16.9,30.9 17.7,30.9
+1V375_VDDSOC_IN: C119.1 C120.1 C121.1 C122.1 C123.1 C124.1 C125.1 C126.1 C127.1 C128.1 C129.1 FB2.1 U1.H16 U1.J16 U1.K16 U1.L16 U1.M16 U1.N16 U1.P16 U1.R16 U1.T16 U1.U16 | length 7.7
  L12 w0.3: C125.1@20.7,26.5 20.7,26.3 21.2,25.8 21.2,25.246 21.9,24.546 C122.1@21.9,24.4 ; C119.1@27.7,25 27.772,25 28.7,24.072 C121.1@28.7,23.6 28.7,23.454 29.3,22.854 v1(29.3,22.8)
  L12 w0.4: C128.1@16.2,26.45 16.85,26.45 v1(17.3,26) ; C126.1@21.9,23.5 C122.1@21.9,24.4
  other v1: 27.7,22 22.9,22.8 24.5,22.8 26.1,22.8 29.3,26.8 18.1,28.4 18.9,28.4
+2V5: C153.1 C233.1 C234.1 C244.1 C245.1 C247.1 FB6.1 L4.1 R14.1 R19.1 R27.1 R34.1 R74.2 R78.2 R80.2 R147.2 TP8.1 U13.10 | length 14.9
  L12 w0.2: v1(63.1,23.1) 63.45,22.75 U13.10@63.45,22.4
  L12 w0.3: R14.1@17.3,10 R14.1@17.4,10 ; R147.2@62.7,24 62.7,23.5 v1(63.1,23.1)
  L12 w0.4: v1(15.4,24.1) 15.4,23.5 C247.1@15.5,23.4 16.121,24.021 16.979,24.021 17.358,24.4 C153.1@17.4,24.4 R80.2@18.5,24.4 ; v1(15.7,17.9) R19.1@16.3,18.5 ; v1(16.3,8.6) C244.1@16.3,9.5 16.558,9.5 17.158,10.1 R14.1@17.3,10.1 ; R78.2@26,9.9 26,9.8 v1(26.4,9.4) 26.9,9.4 R27.1@27.4,9.9 ; v1(29.7,30.2) 30,29.9 R74.2@30,29.6 ; R34.1@33.4,10.6 C245.1@34.7,10.6 34.7,10.1 v1(34.4,9.8)
  L12 w0.45: v1(6.5,26.7) 6.5,27.05 FB6.1@6.9,27.45
  other v1: 61.3,21.5 61.3,22.3 61.6,22.9
+2V5_ETH_DVDDH: C194.1 C195.1 C196.1 C197.1 C198.1 FB6.2 R75.2 R87.2 R89.2 R91.2 R94.2 R95.2 R96.2 R97.2 R98.2 R162.2 U8.16 U8.34 U8.40 | length 18.9
  L1 w0.25: v1(8.1,33) 8.35,33.25 U8.34@9.01,33.25 ; U8.40@11.25,31.51 11.25,30.95 v1(11.4,30.8) ; v1(13.7,39.2) 13.75,39.15 U8.16@13.75,38.49
  L1 w0.3: R87.2@9.6,26.7 v1(9.6,25.8) 9.6,25.5 10.4,24.7 R162.2@11,24.7 ; R89.2@11,29.7 11,30.1 11.4,30.5 v1(11.4,30.8) ; v1(13.5,24.4) 13.6,24.5 R96.2@13.6,25 ; R91.2@13.6,22.5 R97.2@13.6,23.7 v1@13.6,24.4 ; R96.2@13.6,25.1 R75.2@13.6,28.9
  L1 w0.4: v1(18.9,39) 18.9,38.7 19.1,38.5 R94.2@19.525,38.5
  L12 w0.4: C194.1@8.35,33.8 8.1,33.55 v1(8.1,33) C197.1@8.65,32.45 ; C195.1@8.7,31.5 8.7,31.1 v1(9,30.8) ; v1(11.4,30.8) 11.7,31.1 C198.1@11.7,31.4 ; v1(13.7,39.2) C196.1@14.2,38.7
  L12 w0.45: FB6.2@6.9,28.95 7.05,29.1 v1(7.7,29.1)
  other v1: 13.5,25.8
+2V5_VDDHIGH_VPH: C139.2 C140.1 C141.1 U1.H10 U1.J10 | length 6.7
  L12 w0.25: 19.328,17.5 19.478,17.65 19.922,17.65 20.072,17.5 21,17.5 C139.2@21.5,17
  L12 w0.3: C141.1@14.7,16.85 C141.1@14.75,16.8 ; C140.1@18.3,17.5 19.328,17.5 ; C139.2@21.5,17 21.625,17.125 21.625,17.397 21.903,17.675 22.175,17.675 22.5,18 v1(22.9,18)
  L12 w0.4: C141.1@14.7,16.75 14.75,16.8 v1(15.8,16.8)
+3V0_ALWAYS: C87.1 C136.1 C137.1 C142.1 C221.1 C222.1 L3.2 R48.2 R55.2 R60.2 R73.2 R103.2 R104.2 R106.2 R130.2 R138.2 R153.2 R154.2 R165.2 TP11.1 U1.G11 U1.H9 U1.J9 U6.6 U12.10 | length 16.6
  L1 w0.3: R138.2@8.6,4.3 8.9,4.3 v1(9.3,3.9)
  L1 w0.4: v1(21.3,18.8) U1.G11@21.7,18.4
  L1 w0.7: L3.2@13.75,2.5 L3.2@13.85,2.4
  L12 w0.3: R130.2@3.4,25.3 3.7,25.6 v1(4.1,25.6) ; R48.2@5.4,9 6.172,9 6.575,9.403 6.575,9.9 6.4,10.075 v1(6.4,10.6) ; R73.2@5.8,11.3 5.9,11.4 v1(6.4,11.4) 6.7,11.4 7,11.7 R103.2@7,11.9 R55.2@7,13.1 ; v1(9.3,3.9) 9.6,4.2 R106.2@9.9,4.2 ; R104.2@13.4,5.7 13.5,5.8 v1(14.1,5.8) 14.7,5.8 R165.2@14.8,5.7 ; v1(61.7,1.3) R60.2@61.7,2 ; v1(64.2,26.1) R153.2@64.8,26.1 ; v1(65.8,14.3) 66.1,14.6 R154.2@66.1,15
  L12 w0.4: C137.1@14.7,18.75 C137.1@14.8,18.85 ; C142.1@20.7,19 21.1,19 v1(21.3,18.8) ; v1(22.1,17.2) C136.1@22.9,16.4 ; U6.6@64.65,8.75 64.65,8.35 65.2,7.8 C87.1@66,7.8 v1(66.6,7.8)
  other v1: 14.1,5.2 14.7,17.6
+3V3: C1.1 C89.1 C144.1 C146.1 C147.1 C148.1 C154.1 C163.1 C164.1 C165.1 C166.1 C174.1 C177.1 C203.1 C213.1 C214.1 C215.1 FB7.1 J2.50 L1.1 R21.2 R22.2 R28.2 R29.2 R31.2 R32.2 R33.2 R38.2 R39.2 R40.2 R41.2 R42.2 R43.2 R44.2 R45.2 R46.2 R47.2 R49.2 R62.2 R63.2 R64.2 R68.2 R69.2 R76.2 R100.2 R109.1 R110.2 R111.2 R113.2 R114.2 R115.2 R123.2 R129.2 R137.2 TP6.1 U1.G14 U1.G15 U1.G16 U1.G17 U1.J7 U1.K19 U1.L19 U1.M19 U1.P7 U1.P19 U7.5 U9.1 U10.8 U11.10 | length 67
  L1 w0.2: U1.P7@27.3,15.2 27.7,14.8 v1(27.7,14)
  L1 w0.25: v2(25.7,37.3) R29.2@26.3,37.3 ; v2(25.7,38.5) R28.2@26.3,38.5 ; v2(26.2,31.7) R44.2@26.7,31.7 ; v2(26.2,32.9) R45.2@26.7,32.9 ; R62.2@26.3,2.6 v2(26.9,2.6) ; R100.2@29.7,37.3 v2(30.3,37.3) ; R39.2@29.7,38.5 v2(30.3,38.5) ; v2@32.895,2.7 R31.2@33.5,2.7 ; v2@32.908,1.408 R32.2@33.487,1.408
  L1 w0.3: v1(8.3,17.9) 8.4,18 TP6.1@8.4,19.3 ; R63.2@20.6,1.4 20.538,1.4 v1(20.038,1.9) 20.6,2.462 R64.2@20.6,2.6 ; R110.2@21.3,8.4 21.275,8.425 21.275,9.475 21.7,9.9 v1@22.8,9.9 ; v1(24.5,30.2) 24.667,30.2 25.3,30.833 R21.2@25.3,31.7 R137.2@25.3,32.9 ; v1(28.2,35.705) 28.205,35.7 R40.2@29.2,35.7 ; R115.2@32,4 31.482,4 v1(31.3,3.818) 31.3,3.2 R114.2@32.1,2.4 ; R33.2@35,4.1 35.342,3.758 v1(36.043,3.758)
  L1 w0.4: v1(20.1,31) 20.1,31.25 FB7.1@20.65,31.8 20.75,31.7 R111.2@21.8,31.7 ; v1(22.9,14.8) U1.J7@23.3,15.2 ; v1(28,9.43) 28.65,9.43 29.3,8.78 C203.1@29.3,8.2 R109.1@30.4,8.2 ; U10.8@28.05,8.305 C203.1@29.195,8.305 ; R22.2@30.1,33 R38.2@30.1,31.7 30.13,31.67 R49.2@31.575,31.67 31.575,30.925 v1(32.5,30) ; v1(36.087,5.543) 36.087,6.987 R46.2@36.1,7 R47.2@36.1,8.2
  L2 w0.25: v3(25.4,37.6) v2(25.7,37.3) ; v3(25.7,38.1) v2(25.7,38.5) ; v2(26.2,31.7) v3(26.5,32) ; v2(26.2,32.9) v3(26.5,32.6) ; v3(26.6,2.3) v2(26.9,2.6) ; v2(30.3,37.3) v3(30.6,37.6) ; v3(30.3,38.1) v2(30.3,38.5) ; v3(32.888,2.307) v2(32.888,2.707) ; v2(32.9,1.4) v3(33.2,1.7)
  L3 w0.2: v4@29.875,37.95 v4@29.9,37.925
  L3 w0.25: v3(25.4,37.6) 25.3,37.7 v4(25.3,38) 25.4,38.1 v3(25.7,38.1) ; v3(26.5,32) 26.3,32 v4(26,32.3) 26.3,32.6 v3(26.5,32.6) ; v3(26.6,2.3) 27,2.3 v4(27.1,2.4) ; v3(30.3,38.1) 30.075,38.1 29.9,37.925 v4(29.875,37.9) 29.889,37.9 30.189,37.6 v3(30.6,37.6) ; v3(32.888,2.307) 33.31,2.307 33.6,2.017 v4(33.6,1.817) 33.482,1.7 v3(33.2,1.7)
  L12 w0.2: U11.10@6.55,17.6 6.55,16.95 R123.2@7,16.5 ; R123.2@7,16.4 R123.2@7,16.5 ; R123.2@7.1,16.4 R123.2@7,16.5
  L12 w0.28: J2.50@23.25,7.67 23.25,9.35 23.4,9.5
  L12 w0.3: R68.2@1.4,10 1.7,10 v1(2.1,10.4) 2.5,10 R69.2@2.8,10 ; R129.2@6.5,4.4 6.5,4.9 v1(6.7,5.1) 7,5.1 7.5,4.6 R113.2@7.5,4.4
  L12 w0.35: v1(27.7,14) 28.3,14 C163.1@28.9,13.4
  L12 w0.4: R123.2@7.1,16.4 7.6,16.9 v1(8.3,16.9) ; v1(10.4,8.1) 10.6,8.3 R43.2@11.3,8.3 R42.2@11.3,7.1 10.9,6.7 R41.2@10.9,5.6 ; v1(15.3,27.5) 16.35,27.5 C148.1@16.8,27.95 ; C174.1@22.7,14.2 22.7,14.6 v1(22.9,14.8) ; v1(22.9,10) 23.5,10 C1.1@23.7,9.8 23.4,9.5 ; v1(24.5,25.2) 24.5,26.6 ; C144.1@26,26.5 26,25.3 v1(26.1,25.2) ; v1(28,9.43) 28.47,9.9 R76.2@28.6,9.9 29.55,9.9 C147.1@30.05,10.4
  other v1: 4.8,6.8 8,17.4 21.3,22 21.3,22.8 1.3,28.8
+3V3_ETH_AVDDH: C190.1 C199.1 C200.1 C201.1 C202.1 FB7.2 U8.1 U8.12 U8.47 | length 8.8
  L1 w0.2: FB7.2@19.05,31.8 FB7.2@19.15,31.7
  L1 w0.25: U8.47@14.75,31.51 14.75,31.101 15.051,30.8 v1(15.2,30.8) ; U8.1@15.99,32.25 16.65,32.25 v1(16.7,32.3) ; U8.12@15.99,37.75 v1@16.95,37.75
  L1 w0.4: FB7.2@19.15,31.8 19.15,31.7 19.15,31.15 v1(19.3,31)
  L12 w0.4: v1(15.2,30.8) 15,31 C202.1@15,31.4 C190.1@16,31.4 ; C200.1@16.3,33.4 16.7,33 v1(16.7,32.3) ; 16.6,38.7 16.9,38.4 v1(16.9,37.7) ; v1(19.3,31) 19.85,30.45 C199.1@19.85,30.2
+5V_LDO1: C204.1 C205.1 R116.2 R131.2 R132.2 U11.7 | length 13.7
  L12 w0.2: U11.7@7.7,18.75 8.15,18.75 8.9,18 C205.1@8.9,17.6
  L12 w0.4: R131.2@5.8,12.7 R132.2@5.8,13.9 6.1,14.2 7.3,14.2 7.6,14.5 7.6,15.25 C204.1@8.5,16.15 ; 8.975,17 10.6,17 11.1,17.5
  L12 w0.5: C204.1@8.5,16.15 8.9,16.55 C205.1@8.9,17.6 ; 11.1,17.5 11.325,17.725 12.225,17.725 R116.2@13.2,18.7
+5V_LDO2: C223.1 C224.1 R140.2 U13.7 | length 10.4
  L12 w0.2: 62.025,22.3 61.725,22 61.725,21.475 61.95,21.25 U13.7@62.3,21.25
  L12 w0.3: 62.025,22.3 62.2,22.475 62.2,22.7
  L12 w0.4: C223.1@60.35,23.7 60.55,23.5 C224.1@61.6,23.5 61.742,23.5 62.2,23.042 62.2,22.7
  L12 w0.6: R140.2@56.8,22.4 56.8,23.6 57.9,24.7 59.8,24.7 60.35,24.15 C223.1@60.35,23.7
+5V_PVCC1: C206.1 R116.1 R117.2 R118.1 U11.19 | length 16.1
  L3 w0.5: v1(2.2,19.5) 3.187,19.5 3.562,19.875 7.85,19.875 8.4,19.325 10.2,19.325 10.475,19.6 v1(12.5,19.6)
  L12 w0.2: v1(2.2,19.5) 2.45,19.25 U11.19@2.9,19.25
  L12 w0.4: C206.1@1.3,19.6 2.1,19.6 v1(2.2,19.5)
  L12 w0.5: v1(12.5,19.6) 13.1,19.6 R116.1@13.2,19.7 13.1,19.8 R117.2@13.1,21.2 13.1,22.1 R118.1@13.4,22.4
+5V_PVCC2: C225.1 R140.1 R141.2 R142.1 U13.19 | length 21.8
  L3 w0.5: v1(57.5,17.5) 59.7,17.5 60.4,18.2 60.4,19 61,19.6 64.163,19.6 64.538,19.975 65.875,19.975 67.1,21.2 v1(68.9,21.2)
  L12 w0.2: R140.1@56.85,21.05 R140.1@56.9,21.1 ; U13.19@67.1,20.75 68,20.75
  L12 w0.3: 68,20.75 68.25,20.75
  L12 w0.4: 68.25,20.75 C225.1@68.5,20.5 68.9,20.9 v1(68.9,21.2)
  L12 w0.5: R142.1@56.4,16.9 57,17.5 v1(57.5,17.5) 57.5,17.713 56,19.213 56,20.3 56.8,21.1 R140.1@56.8,21.2
+5V_USB_VBUS: C79.1 C82.1 C242.1 J1.18 U1.D10 U1.E9 | length 7.4
  L1 w0.4: U1.D10@19.3,17.6 v1(19.7,17.2) U1.E9@20.1,16.8 ; C242.1@30.6,35.7 31.045,35.7 v1(31.25,35.905)
  L12 w0.2: v1@31.25,35.805 v1(31.25,35.905)
  L12 w0.28: v1(31.25,35.905) J1.18@31.25,38.07
  L12 w0.3: C82.1@17.3,17.4 17.75,16.95 18.55,16.95 C79.1@19.1,16.4
  L12 w0.4: C79.1@19.1,16.4 19.1,16.6 v1(19.7,17.2)
+5V_VCC1: C207.1 R118.2 R127.2 R128.2 U11.3 U11.20 | length 16.5
  L3 w0.5: v1(2.2,20.3) v1@2.207,20.3 ; v1@2.213,20.3 2.7,20.3 3.8,21.4 8,21.4 8.4,21 v1(8.5,20.9)
  L12 w0.2: v1(2.2,20.3) 2.2,20.101 2.551,19.75 U11.20@2.9,19.75 ; U11.3@7.7,20.75 8.35,20.75 v1(8.5,20.9)
  L12 w0.4: v1(8.5,20.9) 9.6,22 C207.1@9.9,22 ; R128.2@11.5,24.5 11.8,24.5 12.2,24.1 R127.2@12.2,23.4
  L12 w0.5: C207.1@9.9,22 9.9,22.3 10.4,22.8 11.142,22.8 11.667,23.325 12.125,23.325 R127.2@12.2,23.4 R118.2@13.4,23.4
+5V_VCC2: C226.1 R142.2 R151.2 R152.2 U13.3 U13.20 | length 17.2
  L3 w0.5: v1(61.3,19) 62.3,18 65.487,18 v1@67.793,20.307
  L12 w0.2: 61.5,19.2 61.55,19.25 U13.3@62.3,19.25 ; U13.20@67.1,20.25 v1@67.75,20.25
  L12 w0.3: v1(61.3,19) 61.5,19.2
  L12 w0.4: R142.2@56.4,15.9 56.7,15.9 57.7,16.9 R152.2@57.9,16.9 58.2,17.2 R151.2@58.2,18.6 58.5,18.6 59,19.1 60.2,19.1 60.7,18.6 C226.1@60.7,18.5 60.8,18.5 v1(61.3,19)
  other v1: 67.8,20.3
+DDR_VREF: C3.1 C4.1 C5.1 C6.1 C7.1 C8.1 C9.1 C10.1 C11.1 C18.2 C20.1 R11.1 R12.2 U1.AC2 U2.H1 U2.M8 U3.H1 U3.M8 U4.H1 U4.M8 U5.H1 U5.M8 | length 168.6
  L1 w0.3: v1(34.1,11.6) U1.AC2@34.5,11.2 ; U2.H1@49.6,5.8 v1(50,5.4) ; U4.H1@49.6,27.8 v1(50,27.4) ; U2.M8@52.8,11.4 v1(53.2,11.8) ; U4.M8@52.8,33.4 v1(53.2,33.8)
  L1 w0.4: v1(50.9,37.2) C8.1@50.9,37.9 ; v1(51,15.2) C3.1@51,15.9 ; C9.1@51,24.1 v1(51,24.8) ; C4.1@53.1,2.1 v1(53.1,2.8)
  L5 (PWR) w0.5: 40.6,14.5 40.6,16.1
  L5 (PWR) w0.6: v1(53.1,2.8) 53.4,3.1
  L5 (PWR) w0.8: v1(34.1,11.6) 38,11.6 40.6,14.2 40.6,14.5 ; 40.6,16.1 40.6,19.8 44,23.2 56.2,23.2 62.825,29.825 62.825,30.325 63.3,30.8 ; v1(50,5.4) 51.3,5.4 52.475,4.225 ; v1(50,12.6) 51,13.6 51,13.775 ; v1(50,27.4) 50.6,26.8 50.6,26.2 ; v1(50,34.6) 50,35.85 50.2,36.05 ; v1@51,24.95 50.6,25.35 50.6,26.2 ; v1@51.1,24.9 52.1,24.9 52.725,25.525 55.825,25.525 61.3,31 61.6,31 ; v1@53.1,3 52.475,3.625 52.475,4.225 ; v1(53.2,6.2) 52.975,6.2 52.475,5.7 52.475,4.225 ; v1(53.2,11.8) 52.975,11.8 51,13.775 ; v1(53.2,28.2) 52.625,28.2 50.625,26.2 50.6,26.2 ; v1(53.2,33.8) 52.975,33.8 51.825,34.95 51.05,34.95 50.2,35.8 50.2,36.05 ; 53.4,3.1 54.4,4.1 58.1,4.1 62.3,8.3 62.3,10.7 64.925,13.325 64.925,17.125 65.7,17.9 65.7,22.275 63.475,24.5 63.475,26.625 65.225,28.375 65.225,29.8 ; 61.6,32.3 60.7,32.3 56.7,36.3 51.8,36.3 v1(50.9,37.2) 50.625,36.925 50.625,36.475 50.2,36.05 ; 63.6,29.9 63.6,28.6 62.325,27.325 62.325,21.3 63.2,20.425 63.2,16 62,14.8 58.9,14.8 57.5,16.2 52,16.2 v1(51,15.2) 51,13.775
  L12 w0.3: U3.H1@49.6,12.2 v1(50,12.6) ; U5.H1@49.6,34.2 v1(50,34.6) ; U3.M8@52.8,6.6 v1(53.2,6.2) ; U5.M8@52.8,28.6 v1(53.2,28.2)
  L12 w0.4: v1(34.1,11.6) 34.2,11.7 C7.1@34.7,11.7 ; v1(50.9,37.2) C10.1@50.9,37.9 ; v1(51,15.2) C5.1@51,15.9 ; C11.1@51,24.1 v1(51,24.8) ; C6.1@53.1,2.1 v1(53.1,2.8)
  other v1: 64.5,31.5
+HDMI_VP: C75.1 R23.2 U1.L7 | length 4.8
  L1 w0.4: v1(24.5,14.8) U1.L7@24.9,15.2
  L12 w0.3: C75.1@23.9,14.4 23.8,14.4 23.3,13.9 23.3,12.9 23.6,12.6 24.6,12.6 R23.2@24.8,12.4
  L12 w0.4: C75.1@23.9,14.4 24.3,14.8 v1(24.5,14.8)
+HDMI_VPH: C76.1 R27.2 U1.M7 | length 5.8
  L1 w0.4: U1.M7@25.7,15.2 v1(26.1,14.8)
  L12 w0.3: C76.1@26.7,13.4 26.1,12.8 26.1,11.728 26.928,10.9 R27.2@27.4,10.9
  L12 w0.35: v1(26.1,14.8) 26.1,14.026 26.7,13.426 C76.1@26.7,13.4
+LVDS_2V5: C77.1 C243.1 R34.2 U1.V7 | length 5.2
  L1 w0.2: U1.V7@30.5,15.2 30.9,14.8 v1(30.9,14)
  L12 w0.3: C77.1@31.4,13.4 31.558,13.4 32.358,12.6 C243.1@32.5,12.6
  L12 w0.4: v1(30.9,14) 31.4,13.5 C77.1@31.4,13.4 ; C243.1@32.5,12.6 32.5,12.1 33,11.6 R34.2@33.4,11.6
+NVCC_CSI: C145.1 R76.1 U1.N7 | length 5.9
  L1 w0.2: U1.N7@26.5,15.2 26.9,14.8 v1@26.9,14.05
  L12 w0.3: C145.1@27.7,13.4 27.3,13 27.3,11.9 27.686,11.514 27.914,11.514 28.528,10.9 R76.1@28.6,10.9
  L12 w0.35: v1(26.9,14) 26.989,14 27.589,13.4 27.7,13.4 C145.1@27.9,13.4
+NVCC_ENET: C155.1 C156.1 R74.1 U1.R19 | length 8.1
  L1 w0.2: v1@27.7,26.1 v1(27.7,26) 27.7,25.2 U1.R19@28.1,24.8
  L12 w0.3: C155.1@27.2,26.5 27.1,26.6 27.75,27.25 27.75,28.8 C156.1@28.35,29.4 ; C156.1@28.45,29.5 28.45,29.234 29.084,28.6 R74.1@29.876,28.6 ; R74.1@30,28.6 R74.1@29.876,28.6 ; R74.1@30.1,28.7 29.976,28.7 R74.1@29.876,28.6
  L12 w0.4: C155.1@27.2,26.6 27.2,26.5 v1(27.7,26)
+NVCC_MIPI: C149.1 R78.1 U1.K7 | length 6.1
  L1 w0.4: U1.K7@24.1,15.2 v1(24.5,15.6)
  L12 w0.3: v1(24.5,15.6) 24.5,15.472 25,14.972 25,14.8 25.1,14.7 25.625,14.175 25.625,13.9 25.8,13.725 25.8,13.175 25.625,13 25.625,12.7 25.5,12.575 25.5,11.4 R78.1@26,10.9
+NVCC_RGMII: C152.1 R80.1 U1.G18 | length 4.4
  L1 w0.4: v1(21.3,24.4) U1.G18@21.7,24
  L12 w0.3: R80.1@18.5,25.4 19.1,24.8 20.2,24.8 C152.1@20.6,25.2 ; C152.1@20.6,25.4 C152.1@20.6,25.2 ; v1(21.3,24.4) 21.3,24.5 C152.1@20.6,25.2
+PCIE_VP: C61.1 R13.2 U1.H7 | length 3.8
  L1 w0.4: v1(22.1,14.8) U1.H7@22.5,15.2
  L12 w0.3: R13.2@20.6,12.2 20.6,12.536 20.9,12.836 20.9,13.6 C61.1@21.5,14.2
  L12 w0.4: C61.1@21.5,14.2 v1(22.1,14.8)
+PCIE_VPH: C64.1 R14.2 U1.G7 | length 2.8
  L1 w0.4: v1(21.3,14.8) U1.G7@21.7,15.2
  L12 w0.3: C64.1@20.3,14.2 20.572,14.2 21.172,14.8 v1(21.3,14.8)
  L12 w0.4: R14.2@18.3,10.1 18.7,10.1 v1(19.1,9.7)
+PCIE_VPTX: C62.1 FB1.2 U1.G8 | length 2.6
  L1 w0.4: U1.G8@21.7,16 v1(22.1,15.6)
  L12 w0.4: v1(21.3,10.8) 22.1,10 FB1.2@22.15,10 ; v1(22.1,15.6) 22.3,15.4 C62.1@22.9,15.4
+SATA_VP: C68.1 R18.2 U1.G13 | length 2.7
  L1 w0.2: v1(21.3,21.2) 21.3,20.4 U1.G13@21.7,20
  L12 w0.4: R18.2@16.6,23.4 17.1,23.4 v1(17.3,23.6) ; C68.1@20.7,21.2 v1(21.3,21.2)
+SATA_VPH: C73.1 R19.2 U1.G12 | length 5
  L1 w0.4: v1(21.3,19.6) U1.G12@21.7,19.2
  L12 w0.3: R19.2@17.3,18.5 17.85,19.05 19.1,19.05 19.25,19.2 C73.1@19.7,19.2
  L12 w0.35: C73.1@19.7,19.2 20.1,19.6 v1(21.3,19.6)
+VDD_SNVS_CAP: C143.1 U1.G9 | length 1.6
  L1 w0.4: v1(21.3,16.4) U1.G9@21.7,16.8
  L12 w0.4: v1(21.3,16.4) 21.5,16.2 C143.1@21.5,15.4
+VDDPU: C130.1 C131.1 C132.1 C133.1 C134.1 C135.1 U1.H17 U1.J17 U1.K17 U1.L17 U1.M17 U1.N17 U1.P17 | length 4.5
  L12 w0.25: 22.3,26.3 22.3,26.1 22.4,26 22.4,25.7 C131.1@22.9,25.2
  L12 w0.3: 22.15,27.05 22.2,27 ; C135.1@22.85,27.5 22.95,27.5 C135.1@23,27.55 ; C131.1@22.9,25.1 22.8,25.2 C131.1@22.9,25.2
  L12 w0.4: 22.3,26.3 22.3,26.9 C132.1@21.7,27.5 22.85,27.5 C135.1@22.9,27.55
  other v1: 22.9,23.6 24.5,23.6 26.1,23.6
+VDDUSB: C80.1 C81.1 U1.F9 | length 2.8
  L1 w0.4: v1(20.5,16.4) U1.F9@20.9,16.8
  L12 w0.4: C80.1@16.6,15.35 17.05,15.35 v1(17.3,15.6) ; C81.1@19.5,15.4 v1(20.5,16.4)
+VIN: C2.1 C208.1 C209.1 C210.1 C220.1 C227.1 C228.1 C229.1 C239.1 C240.1 C241.1 J1.1 J1.2 J1.3 J1.4 J1.5 Q3.8 Q4.8 Q6.8 Q7.8 R117.1 R141.1 U11.6 U12.2 U12.3 U13.6 | length 21.9
  L12 w0.2: U11.6@7.7,19.25 C208.1@9.7,19.25 ; R141.1@56.8,19.6 R141.1@56.9,19.7 ; 61.65,20.75 U13.6@62.3,20.75
  L12 w0.28: J1.5@34.25,32.33 34.25,33.52 v1(34.55,33.82) 34.75,33.62 J1.3@34.75,32.33 ; v1(34.75,36.633) J1.4@34.75,38.07 ; J1.1@35.25,32.33 35.25,34.13 v1(35.275,34.155) ; J1.2@35.25,38.07 35.25,36.932 v1(35.55,36.633)
  L12 w0.3: 61.45,20.75 61.65,20.75
  L12 w0.4: C208.1@9.75,19.2 9.75,19.55 10.5,20.3 11.7,20.3 12.1,20.7 R117.1@12.1,21.2 ; C227.1@60.25,21.6 61.1,20.75 61.45,20.75
  L12 w0.5: R141.1@56.9,19.6 56.9,19.7 56.9,20 57.475,20.575 59.125,20.575 C227.1@60.2,21.65 ; v1(59.8,22.8) 60.25,22.35 C227.1@60.25,21.7
  other v1: 6.8,2.7 6,3.5 6.8,3.5 62.2,3.7 61.6,4.2 62.2,4.7 12.9,8.2 12.9,9 12.4,9.6 8.9,18.7 61.6,35.9 62.2,36.4 36.35,36.633 5.8,36.9 6.6,36.9 7.4,36.9 61.6,36.9
+VREF1_2V_1V5: C238.1 R135.2 U13.1 | length 3.6
  L12 w0.2: 61,17 61,17.3 ; 61.675,17.975 61.95,18.25 U13.1@62.3,18.25
  L12 w0.3: 61.4,17.7 61.675,17.975
  L12 w0.4: C238.1@60.7,17.3 61,17 61.2,16.8 R135.2@61.2,15.9 ; 61,17.3 61.4,17.7
+VREF1_2V_1V375: C219.1 R120.1 U11.1 | length 4.6
  L12 w0.2: U11.1@7.7,21.75 8.45,21.75 9.1,22.4
  L12 w0.3: 9.1,22.4 9.225,22.525
  L12 w0.4: R120.1@8.3,24.6 8.6,24.6 9.4,23.8 C219.1@9.4,23.5 9.4,22.7 9.225,22.525
+VREF1_3V3_1V5: C237.1 R134.2 U13.5 | length 9.4
  L5 (PWR) w0.6: v1(60.6,15.7) 59.9,16.4 59.9,18.6 v1(61.5,20.2)
  L12 w0.2: C237.1@60.7,20.1 60.85,20.25 v1@61.5,20.25 ; v1(61.5,20.2) 61.55,20.25 U13.5@62.3,20.25
  L12 w0.4: v1(60.6,15.7) 60.6,15.2 R134.2@61.2,14.6 ; C237.1@60.7,20 60.9,20.2 v1(61.5,20.2)
+VREF1_3V3_1V375: C218.1 R119.2 U11.5 | length 10.3
  L10 w0.5: v1(8.4,25.3) 7.4,24.3 7.4,20.9 8.4,19.9 v1(8.8,19.9)
  L12 w0.2: U11.5@7.7,19.75 8.65,19.75 v1(8.8,19.9)
  L12 w0.4: R119.2@7.75,26 7.75,25.95 v1(8.4,25.3) ; v1(8.8,19.9) 9.8,20.9 C218.1@9.9,20.9
AUD3_CLK: J2.20 R160.2 | length 4.6
  L1 w0.093: v1(30.75,9.18) 31.22,9.18 31.595,8.805 32.995,8.805 33.212,8.588 R160.2@33.212,8.172
  L12 w0.101: J2.20@30.75,7.67 v1(30.75,9.18)
AUD3_CLK_R: R160.1 U1.T5 | length 10.8
  L1 w0.093: v2(28.5,14) U1.T5@28.9,13.6 ; v2(31.713,8.172) R160.1@32.212,8.172
  L2 w0.1: v3(28.2,13.7) v2(28.5,14) ; v2(31.713,8.172) v3(32.113,8.172)
  L3 w0.08: v3(28.2,13.7) 27.7,13.2 27.7,11.7 28.225,11.175 28.225,10.745 28.8,10.17 29.228,10.17 30.063,9.335 30.063,8.792 30.955,7.9 31.84,7.9 v3(32.113,8.172)
AUD3_RXD: J2.22 U1.N3 | length 11.3
  L1 w0.093: U1.N3@26.5,12 v2(26.9,12.4)
  L2 w0.1: v2(26.9,12.4) v3(26.9,12.8)
  L3 w0.08: v3(26.9,12.8) 26.9,12.13 27.275,11.755 27.275,11.175 26.9,10.8 26.9,10.4 27.425,9.875 27.425,9.192 27.774,8.843 28.552,8.843 28.99,8.405 29.3,8.405 30.188,7.517 v1(30.188,6.242)
  L12 w0.093: v1(30.188,6.242) 30.25,6.305 J2.22@30.25,7.67
AUD3_TXC: J2.16 R72.2 | length 6
  L1 w0.093: v1(31.813,9.18) 31.868,9.125 33.43,9.125 33.875,8.68 33.875,7.243 33.618,6.985 R72.2@33.213,6.985
  L12 w0.101: J2.16@31.75,7.67 31.75,9.117 v1(31.813,9.18)
AUD3_TXC_R: R72.1 U1.N1 | length 8.3
  L1 w0.093: U1.N1@26.5,10.4 26.9,10 v2(27.6,10) ; v2(31.713,6.985) R72.1@32.213,6.985
  L2 w0.1: v2(27.6,10) v3(27.9,10.3) ; v2(31.713,6.985) v3(32.113,6.985)
  L3 w0.08: v3(27.9,10.3) 27.9,10.06 29.155,8.805 29.566,8.805 31.386,6.985 v3(32.113,6.985)
AUD3_TXD: J2.18 U1.P2 | length 9
  L1 w0.093: v2(26.913,10.8) U1.P2@27.313,11.2
  L2 w0.1: v2(26.913,10.8) v3(27.213,10.5)
  L3 w0.08: v3(27.213,10.5) 27.625,10.088 27.625,9.275 27.857,9.043 28.635,9.043 29.072,8.605 29.433,8.605 30.45,7.588 30.45,7.227 31.25,6.427 v1(31.25,6.242)
  L12 w0.093: v1(31.25,6.242) J2.18@31.25,7.67
AUD3_TXFS: J2.24 U1.N4 | length 8.6
  L1 w0.093: U1.N4@26.5,12.8 26.9,13.2 v2(27.7,13.2)
  L2 w0.1: v3(27.3,13.2) v2(27.7,13.2)
  L3 w0.08: v3(27.3,13.2) 27.3,12.013 27.5,11.813 27.5,11.117 28.2,10.417 28.2,10.143 29.163,9.18 v1(29.688,9.18)
  L12 w0.093: v1(29.688,9.18) 29.75,9.118 J2.24@29.75,7.67
BOARD_VARIANT_0: R111.1 R143.2 U1.G24 | length 5.4
  L1 w0.093: U1.G24@21.7,28.8 21.3,29.2 21.3,30.63 21.585,30.915 22.415,30.915 22.8,31.3 R111.1@22.8,31.7 R143.2@22.8,32.9
BOARD_VARIANT_1: R137.1 R144.2 U1.H25 | length 7.4
  L1 w0.093: U1.H25@22.5,29.6 23.75,30.85 23.75,32.75 23.9,32.9 R137.1@24.3,32.9 24.3,33.5 24.7,33.9 25.2,33.9 25.5,34.2 25.5,34.5 25.7,34.7 R144.2@26.1,34.7
BOOT_MODE: J1.50 Q9.1 R165.1 | length 57.8
  L10 w0.08: v6(13.25,2.4) 13.05,2.2 11.202,2.2 10.902,2.5 9.2,2.5 8.583,3.117 8.583,3.917 8.4,4.1 8.4,6.3 8,6.7 8,10 7.5,10.5 7.5,12.203 7.1,12.603 7.1,14.6 7.3,14.8 7.3,16.8 7.6,17.1 7.6,19.5 6.6,20.5 6.6,23.8 6.75,23.95 6.75,24.616 8.4,26.266 8.896,26.266 12.63,30 15.4,30 17.075,31.675 17.075,33.475 17.175,33.575 17.175,34.679 21.821,39.325 23.308,39.325 v6(23.55,39.083)
  L11 w0.1: v6(13.25,2.4) v5(13.65,2.4) ; v5(23.25,39.383) v6(23.55,39.083)
  L12 w0.093: v5(13.65,2.4) Q9.1@13.65,2.95 13.65,3.45 14,3.8 14.5,3.8 14.8,4.1 R165.1@14.8,4.7 ; J1.50@23.25,38.07 v5(23.25,39.383)
BOOT_MODE0: Q9.3 R58.2 R104.1 U1.C12 | length 39.1
  L1 w0.093: v2(18.1,19.6) U1.C12@18.5,19.2
  L2 w0.1: v2(18.1,19.6) v3(18.4,19.3)
  L3 w0.08: v4(10.3,1.4) 10.025,1.675 8.075,1.675 7.7,1.3 6.6,1.3 6.4,1.5 6.4,4.175 7.225,5 7.225,10.305 6.53,11 6.27,11 6,11.27 6,13.604 7.926,15.53 8.265,15.53 9.459,16.725 11.608,16.725 12.25,17.367 12.25,17.833 13.317,18.9 15.8,18.9 16.3,19.4 18.3,19.4 v3(18.4,19.3)
  L10 w0.08: v4(10.3,1.4) v6(10.75,1.4)
  L11 w0.1: v6(10.75,1.4) v5(11.05,1.7)
  L12 w0.093: v5(11.05,1.7) 11.65,2.3 Q9.3@11.75,2.3 11.75,4.35 R58.2@12.1,4.7 R104.1@13.4,4.7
